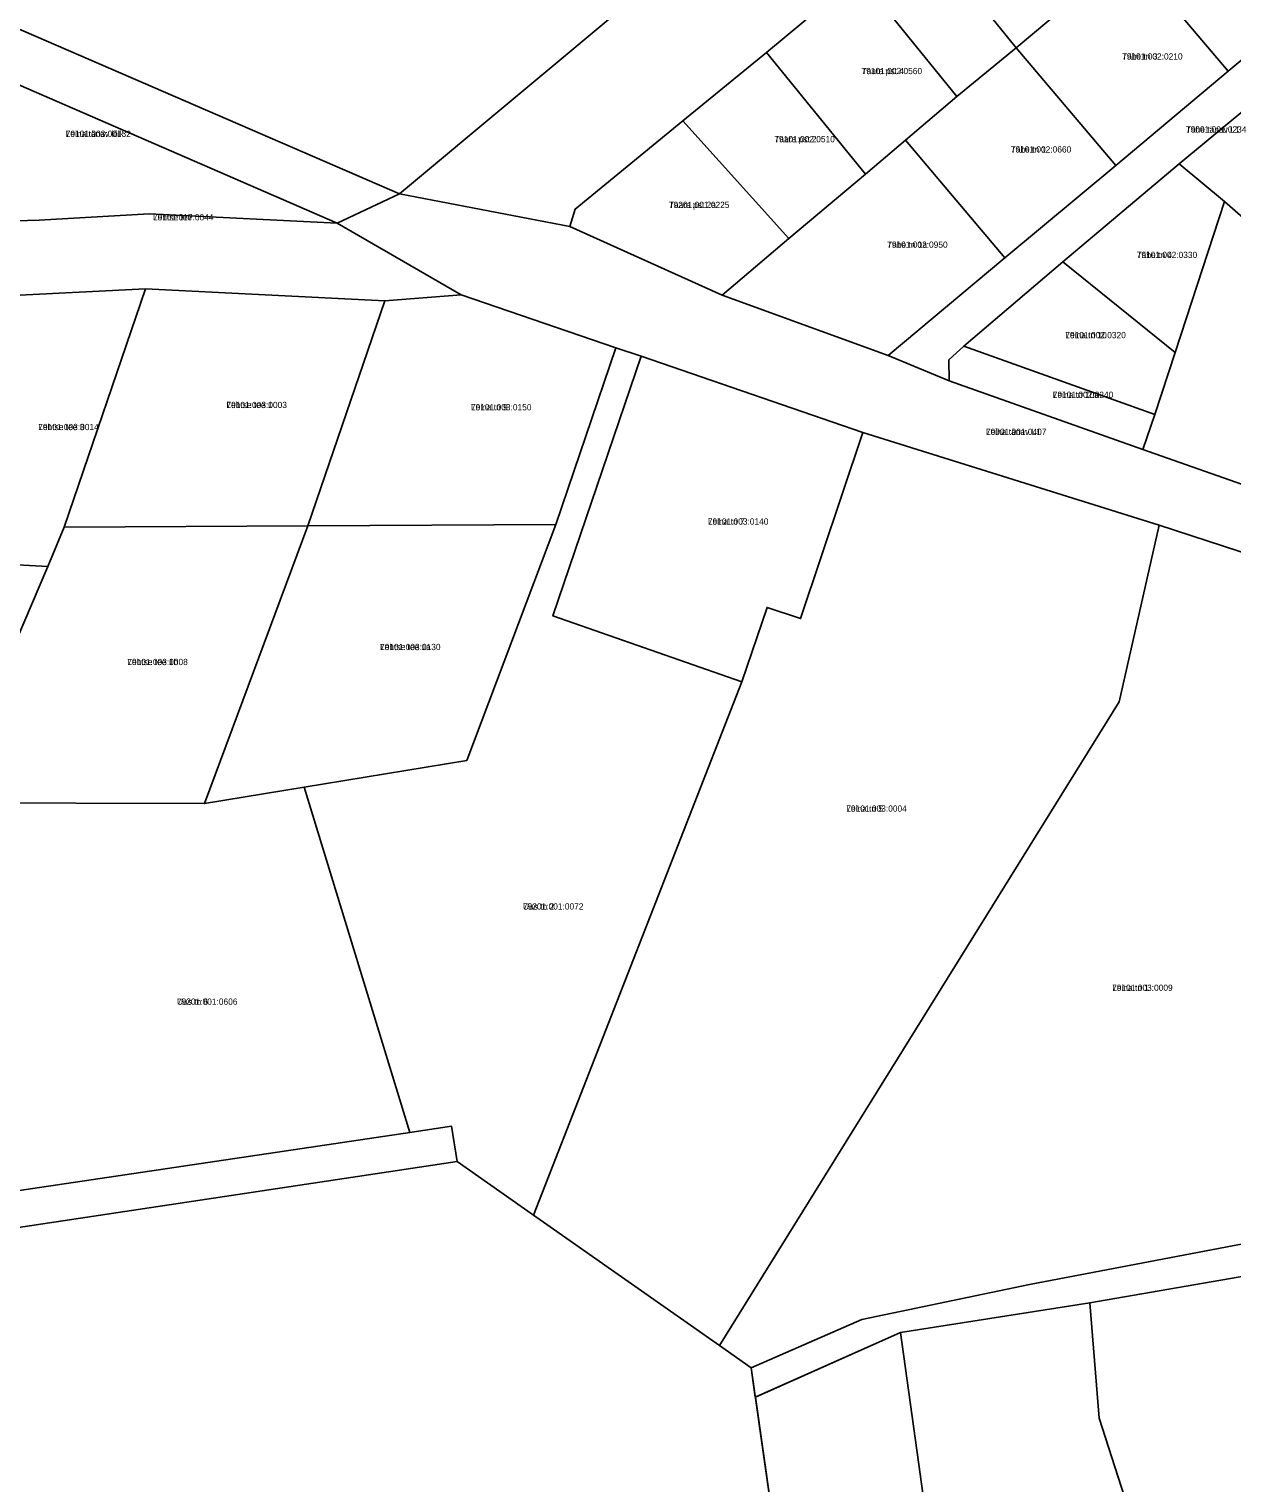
# Model space of a CAD drawing. Extents: x 587616 to 632239, y 6547421 to 6574977.
# Drawn here: x 611262 to 611550.3, y 6571383.6 to 6571731.9 of the extents above; entities that cross this region are included whole.
import ezdxf

# ---------------------------------------------------------------- set-up
doc = ezdxf.new("R2010")
doc.units = 0
for name, color, linetype in [('L_AADRESS', 7, 'Continuous'), ('PIIR', 7, 'Continuous'), ('TUNNUS', 7, 'Continuous')]:
    doc.layers.add(name, color=color, linetype=linetype)

msp = doc.modelspace()

# ---------------------------------------------------------------- linework, layer by layer
at = {"layer": 'PIIR'}
for points in [[(611434.88, 6571762.6), (611350.81, 6571692.38), (611258.33, 6571732.44), (611285.64, 6571795.35), (611357.86, 6571855.59)], [(611258.33, 6571732.44), (611350.81, 6571692.38), (611335.83, 6571685.38), (611240.54, 6571726.73), (611106, 6571785.11), (611067.07, 6571801.69), (611080.99, 6571809.57), (611246.61, 6571737.64)], [(611475.22, 6571756.23), (611501.52, 6571778.34), (611525.48, 6571749.97), (611498.55, 6571727.41)], [(611482.43, 6571652.66), (611482.5, 6571647.61), (611467.85, 6571653.71), (611495.88, 6571677.1), (611522.47, 6571699.21), (611549.36, 6571721.82), (611562.77, 6571733), (611576.4, 6571744.42), (611602.7, 6571766.58), (611609.2, 6571759), (611566.71, 6571723.63), (611537.62, 6571699.64), (611509.76, 6571676.11), (611486.04, 6571655.92)], [(611539.08, 6571761.41), (611562.77, 6571733), (611549.36, 6571721.82), (611525.48, 6571749.97)], [(611475.22, 6571756.23), (611498.55, 6571727.41), (611484.34, 6571715.72), (611460.84, 6571744.72)], [(611522.47, 6571699.21), (611498.55, 6571727.41), (611525.48, 6571749.97), (611549.36, 6571721.82)], [(611460.84, 6571744.72), (611484.34, 6571715.72), (611472.08, 6571705.27), (611462.49, 6571697.1), (611438.7, 6571726.29)], [(611240.54, 6571726.73), (611335.83, 6571685.38), (611290.79, 6571687.59), (611264.43, 6571686.14), (611250.17, 6571685.74), (611255.26, 6571698.71), (611251.7, 6571712.8)], [(611462.49, 6571697.1), (611444.06, 6571681.75), (611418.72, 6571709.92), (611438.7, 6571726.29)], [(611472.08, 6571705.27), (611484.34, 6571715.72), (611498.55, 6571727.41), (611522.47, 6571699.21), (611495.88, 6571677.1)], [(611566.71, 6571723.63), (611586.2, 6571700.5), (611607.39, 6571675.16), (611573.94, 6571668.3), (611548.52, 6571690.61), (611537.62, 6571699.64)], [(611391.61, 6571684.58), (611392.88, 6571688.78), (611418.72, 6571709.92), (611444.06, 6571681.75), (611428.08, 6571668.12)], [(611462.49, 6571697.1), (611472.08, 6571705.27), (611495.88, 6571677.1), (611467.85, 6571653.71), (611428.08, 6571668.12), (611444.06, 6571681.75)], [(611537.62, 6571699.64), (611548.52, 6571690.61), (611536.65, 6571654.41), (611509.76, 6571676.11)], [(611655.13, 6571591), (611636.79, 6571576.94), (611634.42, 6571579.97), (611594.05, 6571593.1), (611532.8, 6571613.07), (611461.84, 6571635.23), (611408.7, 6571653.51), (611402.66, 6571655.56), (611365.53, 6571668.22), (611335.83, 6571685.38), (611350.81, 6571692.38), (611391.61, 6571684.58), (611428.08, 6571668.12), (611467.85, 6571653.71), (611482.5, 6571647.61), (611528.92, 6571631.13), (611557.1, 6571621.3), (611585.56, 6571611.3), (611610.8, 6571602.83), (611645.3, 6571591.28)], [(611548.52, 6571690.61), (611573.94, 6571668.3), (611557.1, 6571621.3), (611528.92, 6571631.13), (611531.76, 6571639.56), (611536.65, 6571654.41)], [(611509.76, 6571676.11), (611536.65, 6571654.41), (611531.76, 6571639.56), (611486.04, 6571655.92)], [(611289.91, 6571669.62), (611270.41, 6571612.56), (611266.47, 6571603.14), (611238.51, 6571604.64), (611259.7, 6571668.14)], [(611289.91, 6571669.62), (611347.25, 6571666.8), (611328.79, 6571612.87), (611270.41, 6571612.56)], [(611365.53, 6571668.22), (611402.66, 6571655.56), (611388.23, 6571613.18), (611328.79, 6571612.87), (611347.25, 6571666.8)], [(611402.66, 6571655.56), (611408.7, 6571653.51), (611387.53, 6571591.32), (611432.8, 6571575.48), (611382.92, 6571447.77), (611364.62, 6571460.57), (611363.25, 6571469.04), (611353.26, 6571467.56), (611327.94, 6571550.27), (611366.88, 6571556.67), (611388.23, 6571613.18)], [(611528.92, 6571631.13), (611482.5, 6571647.61), (611482.43, 6571652.66), (611486.04, 6571655.92), (611531.76, 6571639.56)], [(611461.84, 6571635.23), (611446.88, 6571590.68), (611438.88, 6571593.32), (611432.8, 6571575.48), (611387.53, 6571591.32), (611408.7, 6571653.51)], [(611461.84, 6571635.23), (611532.8, 6571613.07), (611523.27, 6571570.76), (611427.47, 6571416.49), (611382.92, 6571447.77), (611432.8, 6571575.48), (611438.88, 6571593.32), (611446.88, 6571590.68)], [(611270.41, 6571612.56), (611328.79, 6571612.87), (611304.01, 6571546.34), (611242.32, 6571546.54), (611266.47, 6571603.14)], [(611328.79, 6571612.87), (611388.23, 6571613.18), (611366.88, 6571556.67), (611327.94, 6571550.27), (611304.01, 6571546.34)], [(611532.8, 6571613.07), (611594.05, 6571593.1), (611611.55, 6571584.74), (611615.68, 6571578.3), (611609.39, 6571559.45), (611599.5, 6571533.83), (611577.25, 6571492.16), (611581.04, 6571446.26), (611501.79, 6571431.16), (611461.56, 6571422.77), (611435.05, 6571411.17), (611427.47, 6571416.49), (611523.27, 6571570.76)], [(611206.1, 6571606.48), (611238.51, 6571604.64), (611266.47, 6571603.14), (611242.32, 6571546.54), (611241.08, 6571553), (611236.96, 6571574.95), (611232.84, 6571597.14), (611207.29, 6571593.35)], [(611248.94, 6571508.1), (611245.41, 6571530.62), (611244.54, 6571535.14), (611242.32, 6571546.54), (611304.01, 6571546.34), (611327.94, 6571550.27), (611353.26, 6571467.56), (611208.54, 6571446.04), (611203.59, 6571475.14), (611254.44, 6571481.73)], [(611034.93, 6571416.99), (611002.58, 6571413.7), (611006.64, 6571428.41), (611037.62, 6571432.59), (611067.12, 6571436.64), (611095.76, 6571440.54), (611105.57, 6571430.96), (611129.05, 6571434.3), (611165.47, 6571439.68), (611198.94, 6571444.55), (611208.54, 6571446.04), (611353.26, 6571467.56), (611363.25, 6571469.04), (611364.62, 6571460.57), (611206.85, 6571436.9), (611097.41, 6571417.73), (611097.14, 6571422.94)], [(610865.56, 6571276.29), (611007.31, 6571371.33), (611002.58, 6571413.7), (611034.93, 6571416.99), (611097.14, 6571422.94), (611097.41, 6571417.73), (611206.85, 6571436.9), (611364.62, 6571460.57), (611382.92, 6571447.77), (611427.47, 6571416.49), (611435.05, 6571411.17), (611448.89, 6571314.17), (611203.05, 6571275.05), (611170.31, 6571268.86), (611170.38, 6571268.33), (611164.27, 6571267.16), (611144.88, 6571264.4), (611088.37, 6571254.96), (610941.36, 6571230.58), (610934.08, 6571261.97), (610872.16, 6571247.51)], [(611563, 6571335.15), (611552.64, 6571333.21), (611546.75, 6571367.42), (611528.35, 6571368.37), (611518.46, 6571399.08), (611516.25, 6571426.74), (611555.89, 6571433.64), (611565.92, 6571384.12), (611586.1, 6571385.69)], [(611470.81, 6571419.63), (611516.25, 6571426.74), (611518.46, 6571399.08), (611528.35, 6571368.37), (611533.89, 6571329.77), (611534.23, 6571327.47), (611484.78, 6571319.38), (611484.57, 6571320.68)], [(611470.81, 6571419.63), (611484.57, 6571320.68), (611448.89, 6571314.17), (611436.06, 6571404.12)]]:
    msp.add_lwpolyline(points, close=True, dxfattribs=at)
for points in [[(611460.84, 6571744.72), (611438.7, 6571726.29), (611418.72, 6571709.92), (611392.88, 6571688.78), (611391.61, 6571684.58), (611350.81, 6571692.38), (611434.88, 6571762.6)], [(611250.17, 6571685.74), (611264.43, 6571686.14), (611290.79, 6571687.59), (611335.83, 6571685.38), (611365.53, 6571668.22), (611347.25, 6571666.8), (611289.91, 6571669.62), (611259.7, 6571668.14)], [(611839.32, 6571486.94), (611766.34, 6571475.32), (611716.33, 6571465.18), (611671.18, 6571455.7), (611661.77, 6571453.6), (611637.31, 6571448.31), (611581.9, 6571439.5), (611555.89, 6571433.64), (611516.25, 6571426.74), (611470.81, 6571419.63), (611436.05, 6571404.12), (611435.05, 6571411.17), (611461.56, 6571422.77), (611501.79, 6571431.16), (611581.04, 6571446.26), (611628.68, 6571456.69), (611636.22, 6571458.32), (611675.11, 6571466.23), (611692.92, 6571467.43), (611708.42, 6571470.43), (611776.13, 6571483.99)]]:
    msp.add_lwpolyline(points, dxfattribs=at)

# ---------------------------------------------------------------- texts
at = {"layer": 'L_AADRESS'}
for s, p in [('Tähe tn 3', (611523.95, 6571724.58)), ('Taara pst 4', (611461.52, 6571721.09)), ('Tähe tänav L1', (611539.25, 6571707.09)), ('Leina tänav lõik 2', (611270.79, 6571706.05)), ('Taara pst 2', (611440.61, 6571704.77)), ('Tähe tn 1', (611497.27, 6571702.31)), ('Taara pst 2a', (611415.35, 6571689.02)), ('Lehtse tee', (611291.7, 6571686.05)), ('Tähe tn 1a', (611467.64, 6571679.49)), ('Tähe tn 4', (611527.45, 6571677.03)), ('Leina tn 10', (611510.35, 6571657.83)), ('Leina tn 10a', (611507.34, 6571643.53)), ('Lehtse tee 1', (611309.3, 6571641.09)), ('Leina tn 9', (611367.91, 6571640.54)), ('Lehtse tee 3', (611264.21, 6571635.81)), ('Leina tänav L1', (611491.32, 6571634.66)), ('Leina tn 7', (611424.69, 6571613.17)), ('Lehtse tee 1a', (611346.12, 6571583.11)), ('Lehtse tee 1b', (611285.55, 6571579.52)), ('Leina tn 5', (611457.86, 6571544.4)), ('Uus tn 2', (611380.37, 6571520.96)), ('Leina tn 1', (611521.57, 6571501.48)), ('Uus tn 6', (611297.45, 6571498.15))]:
    msp.add_text(s, height=1.5, dxfattribs=at).set_placement(p)
at = {"layer": 'TUNNUS'}
for s, p in [('79101:002:0210', (611523.95, 6571724.58)), ('79101:002:0560', (611461.52, 6571721.09)), ('79001:001:0234', (611539.25, 6571707.09)), ('79101:003:0013', (611270.79, 6571706.05)), ('79101:002:0510', (611440.61, 6571704.77)), ('79101:002:0660', (611497.27, 6571702.31)), ('79201:001:0225', (611415.35, 6571689.02)), ('79101:017:0044', (611291.7, 6571686.05)), ('79101:002:0950', (611467.64, 6571679.49)), ('79101:002:0330', (611527.45, 6571677.03)), ('79101:002:0320', (611510.35, 6571657.83)), ('79101:003:0003', (611309.3, 6571641.09)), ('79101:003:0150', (611367.91, 6571640.54)), ('79101:002:0240', (611507.34, 6571643.53)), ('79101:003:0014', (611264.21, 6571635.81)), ('79001:001:0407', (611491.32, 6571634.66)), ('79101:003:0140', (611424.69, 6571613.17)), ('79101:003:0130', (611346.12, 6571583.11)), ('79101:003:0008', (611285.55, 6571579.52)), ('79101:003:0004', (611457.86, 6571544.4)), ('79201:001:0072', (611380.37, 6571520.96)), ('79101:003:0009', (611521.57, 6571501.48)), ('79201:001:0606', (611297.45, 6571498.15))]:
    msp.add_text(s, height=1.5, dxfattribs=at).set_placement(p)

doc.saveas('drawing.dxf')
